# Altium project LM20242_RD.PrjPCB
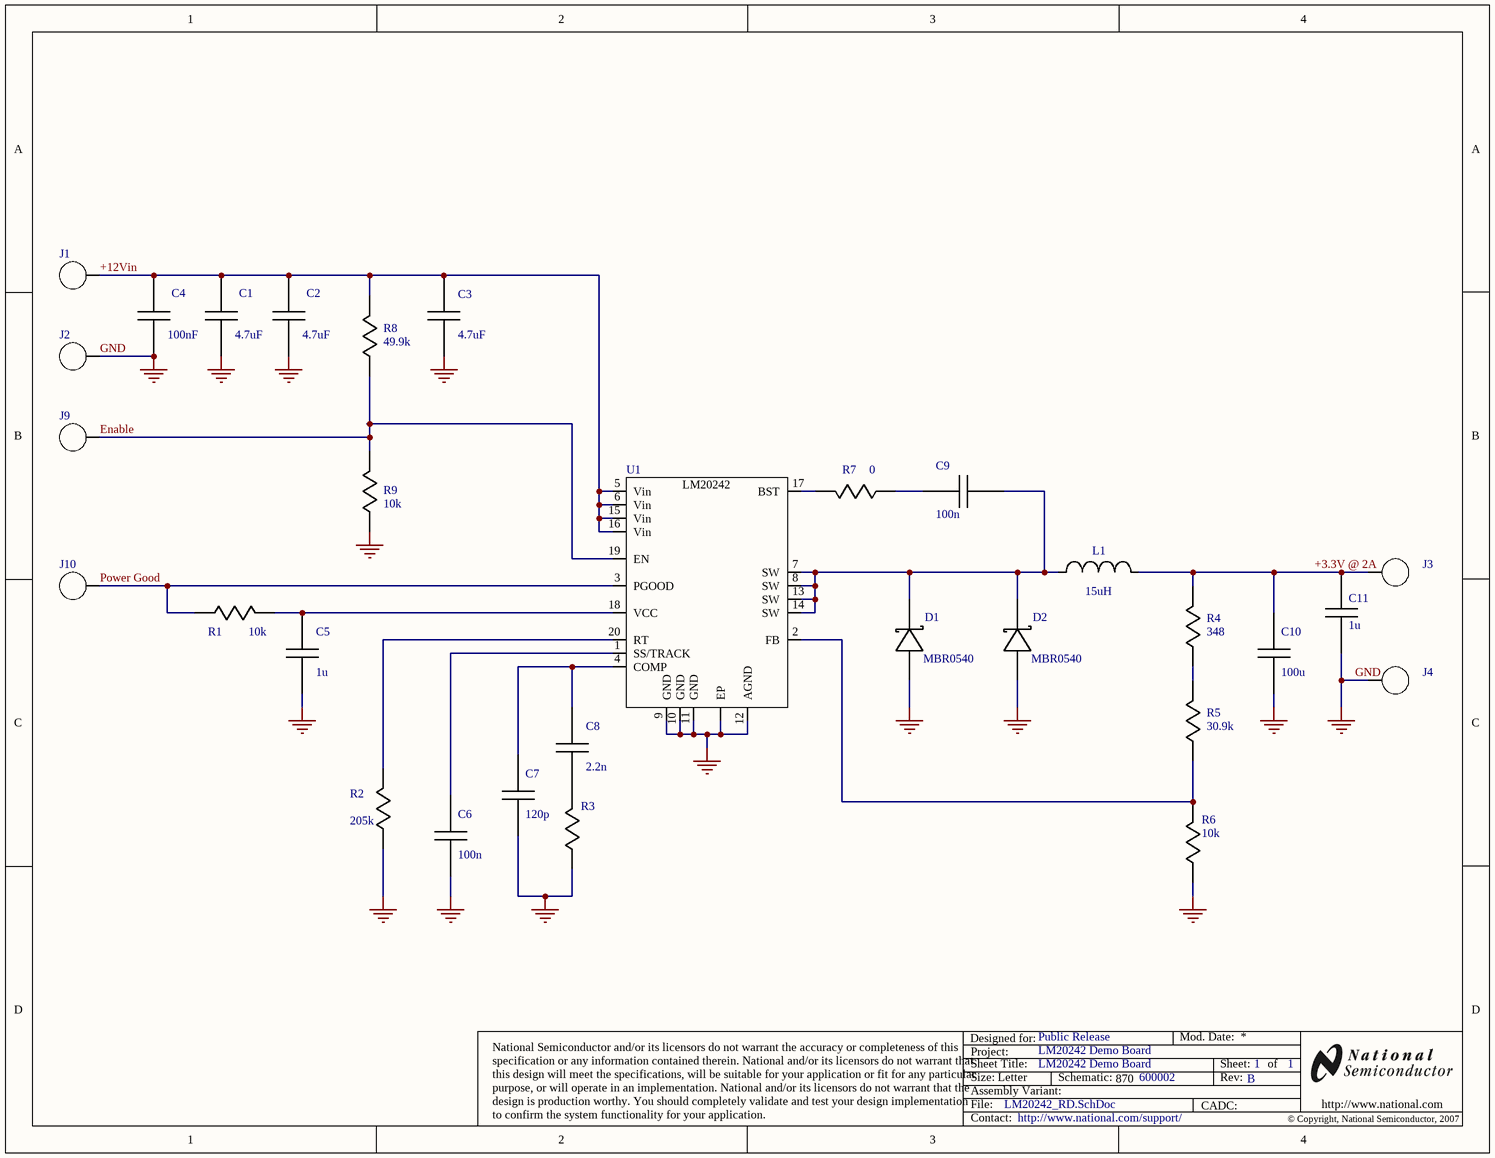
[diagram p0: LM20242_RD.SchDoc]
SCH_Rev: B; PRJ_Title: LM20242 Demo Board; PRJ_Customer: Public Release; PRJ_BasePN: 600002
1 sheet, 30 parts. Net scope: global (net labels, ports and power ports of the same name join across sheets).
Board file: LM20242_Demo_Board_RevB.PcbDoc

## Sheet LM20242_RD.SchDoc: LM20242 Demo Board
size Letter; PageSetup: Record=PageOptions|CenterHorizontal=True|CenterVertical=True|PrintScale=0.97|XCorrection=1.00|YCorrection=1.00|PrintKind=1|BorderSize=5000000|LeftOffset=0|BottomOffset=0|Orientation=2|PaperLength=1000|PaperWidth=1000|Scale=100|PaperSource=15|PrintQuality=1200|MediaType=1|DitherType=10|PaperKind=Letter|PrintScaleMode=1; Author: National Engineer; CompanyName: National Semiconductor; Revision: A; SheetNumber: 1; SheetTotal: 1; URL: http://www.national.com; TechSupport: http://www.national.com/support/

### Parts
C1  value 4.7uF  [1210]  (hidden comment: WB_CAPACITOR)
C2  value 4.7uF  [1210]  (hidden comment: WB_CAPACITOR)
C3  value 4.7uF  [1210]  (hidden comment: WB_CAPACITOR)
C4  value 100nF  [0805]  (hidden comment: WB_CAPACITOR)
C5  Cap (F): 1u  [0603]  (hidden comment: WB_CAPACITOR)
C6  Cap (F): 100n  [0603]  (hidden comment: WB_CAPACITOR)
C7  Cap (F): 120p  [0603]  (hidden comment: WB_CAPACITOR)
C8  Cap (F): 2.2n  [0603]  (hidden comment: WB_CAPACITOR)
C9  Cap (F): 100n  [0603]  (hidden comment: WB_CAPACITOR)
C10  Cap (F): 100u  [1210]  (hidden comment: WB_CAPACITOR)
C11  Cap (F): 1u  [0805]
D1  (no value)  [SOD-123]
D2  (no value)  [SOD-123]
J1  Turret terminal, double  [TURRET]  (value not drawn)
J2  Turret terminal, double  [TURRET]  (value not drawn)
J3  Turret terminal, double  [TURRET]  (value not drawn)
J4  Turret terminal, double  [TURRET]  (value not drawn)
J9  Through Hole Test Point, Miniature, White  [TESTPOINT]  (value not drawn)
J10  Through Hole Test Point, Miniature, White  [TESTPOINT]  (value not drawn)
L1  value 15uH  [MSS1278]
R1  Res (ohm): 10k  [0603]
R2  Res (ohm): 205k  [0603]
R3  (no value)  [0603]
R4  Res (ohm): 348  [0603]
R5  Res (ohm): 30.9k  [0603]
R6  Res (ohm): 10k  [0603]
R7  Res (ohm): 0  [0603]
R8  Res (ohm): 49.9k  [0603]
R9  Res (ohm): 10k  [0603]
U1  (no value)  [MXA20A]

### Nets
GND: C1.2 C2.2 C3.2 C4.2 C5.2 C6.2 C7.2 C10.2 C11.2 D1.1(A) D2.1(A) J2.1 J4.1 R2.2 R3.2 R6.2 R9.2 U1.9(GND) U1.10(GND) U1.11(GND) U1.12(AGND) U1.21(EP)
+3.3V @ 2A: C10.1 C11.1 J3.1 L1.1 R4.1
+12Vin: C1.1 C2.1 C3.1 C4.1 J1.1 R8.1 U1.5(Vin) U1.6(Vin) U1.15(Vin) U1.16(Vin)
Enable: J9.1 R8.2 R9.1 U1.19(EN)
Power Good: J10.1 R1.2 U1.3(PGOOD)
NetC5_1: C5.1 R1.1 U1.18(VCC)
NetC6_1: C6.1 U1.1(SS/TRACK)
NetC7_1: C7.1 C8.1 U1.4(COMP)
NetC8_2: C8.2 R3.1
NetC9_1: C9.1 R7.2
NetC9_2: C9.2 D1.2(K) D2.2(K) L1.2 U1.7(SW) U1.8(SW) U1.13(SW) U1.14(SW)
NetR2_1: R2.1 U1.20(RT)
NetR4_2: R4.2 R5.1
NetR5_2: R5.2 R6.1 U1.2(FB)
NetR7_1: R7.1 U1.17(BST)

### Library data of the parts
C1-C3 = GRM32ER71H475K: Capacitor; Cap (F): 4.7u; Vendor: MuRata; Tolerance (%): 10; VDC (V): 50; Value2: 50V; ESR (Ohm): 0.005; Value1: 0.005Ohms; IRMS (A): 3.7; TaMin (C): -55; TaMax (C): 125; Polarized: N; dielectric: X7R
C4 = C2012X7R2A104K: Capacitor; Cap (F): 100n; Vendor: TDK; Tolerance (%): 10; VDC (V): 100; Value2: 100V; ESR (Ohm): 0; Value1: 0Ohms; TaMin (C): -55; TaMax (C): 125; Polarized: N; dielectric: X7R
C5 = WB_CAPACITOR: Capacitor; PartNumber: GRM188R71A105KA61D; Polarized: N; Tolerance (%): 10; Vendor: MuRata; dielectric: X7R
C6 C9 = WB_CAPACITOR: Capacitor; PartNumber: C1608X7R1H104K; Polarized: N; Tolerance (%): 10; VDC (V): 50; Vendor: TDK; dielectric: X7R
C7 = WB_CAPACITOR: Capacitor; PartNumber: C1608C0G1H121J; Polarized: N; Tolerance (%): 5; VDC (V): 50; Vendor: TDK; dielectric: C0G
C8 = WB_CAPACITOR: Capacitor; PartNumber: C1608C0G1H222J; Polarized: N; Tolerance (%): 5; VDC (V): 50; Vendor: TDK; dielectric: C0G
C10 = WB_CAPACITOR: Capacitor; PartNumber: C1210C107M9PAC; Polarized: N; Tolerance (%): 20; VDC (V): 6.3; Vendor: Kemet; dielectric: X5R
C11 = WB_CAPACITOR: Capacitor; PartNumber: GRM21BR71H105KA12L; Polarized: N; Tolerance (%): 10; VDC (V): 50; Vendor: MuRata; dielectric: X7R
D1 D2 = MBR0540: Schottky Diode; Vf (V): 0.51; Vendor: Fairchild; Io (A): 0.5; Value: 0.51V; Vr (V): 40; TJmax (C): 150; RJC (C/W): 118; Symbol Name: WB_DIODE_SCHOTTKY
J1-J4 = WB_TURRET: TURRET; PartNumber: 1503-2; Vendor: Keystone
J9 J10 = WB_TESTPOINT: TEST POINT; PartNumber: 5002; Vendor: Keystone
L1 = MSS1278-153: Inductor; Vendor: Coilcraft Inc.; L (H): 15u; DCR (Ohms): 0.038; IDC (A): 6.5; Material: Ferrite; Symbol Name: WB_INDUCTOR; Value1: 0
R1 R6 R9 = WB_RESISTOR: Resistor; PartNumber: CRCW06031002F; Power (W): 0.1; Tolerance (%): 1; Vendor: Vishay
R2 = WB_RESISTOR: Resistor; PartNumber: CRCW06032053F; Power (W): 0.1; Tolerance (%): 1; Vendor: Vishay
R3 = WB_RESISTOR: Resistor; PartNumber: CRCW06031212F; Res (ohm): 12.1k; Power (W): 0.1; Tolerance (%): 1; Vendor: Vishay
R4 = WB_RESISTOR: Resistor; PartNumber: CRCW0603348RF; Power (W): 0.1; Tolerance (%): 1; Vendor: Vishay
R5 = WB_RESISTOR: Resistor; PartNumber: CRCW06033092F; Power (W): 0.1; Tolerance (%): 1; Vendor: Vishay
R7 = WB_RESISTOR: Resistor; PartNumber: CRCW06030000Z0EA; Power (W): 0.1; Vendor: Vishay
R8 = WB_RESISTOR: Resistor; PartNumber: CRCW06034992F; Power (W): 0.1; Tolerance (%): 1; Vendor: Vishay
U1 = LM20242: 36V, 2A Step-Down Synchronous Switching Regulator; CompType: Switcher; Vendor: National Semiconductor

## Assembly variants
LM20242 Demo Board: all parts fitted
